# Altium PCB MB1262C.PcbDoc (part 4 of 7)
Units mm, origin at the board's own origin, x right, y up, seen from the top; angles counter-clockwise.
Board outline 208 x 250 mm, 6 copper layers (Top Layer, Layer 2, Layer 3, Layer 4, Layer 5, Bottom Layer), stack 1.596 mm thick; 483 components, 502 nets, 2134 pads, 1709 vias.
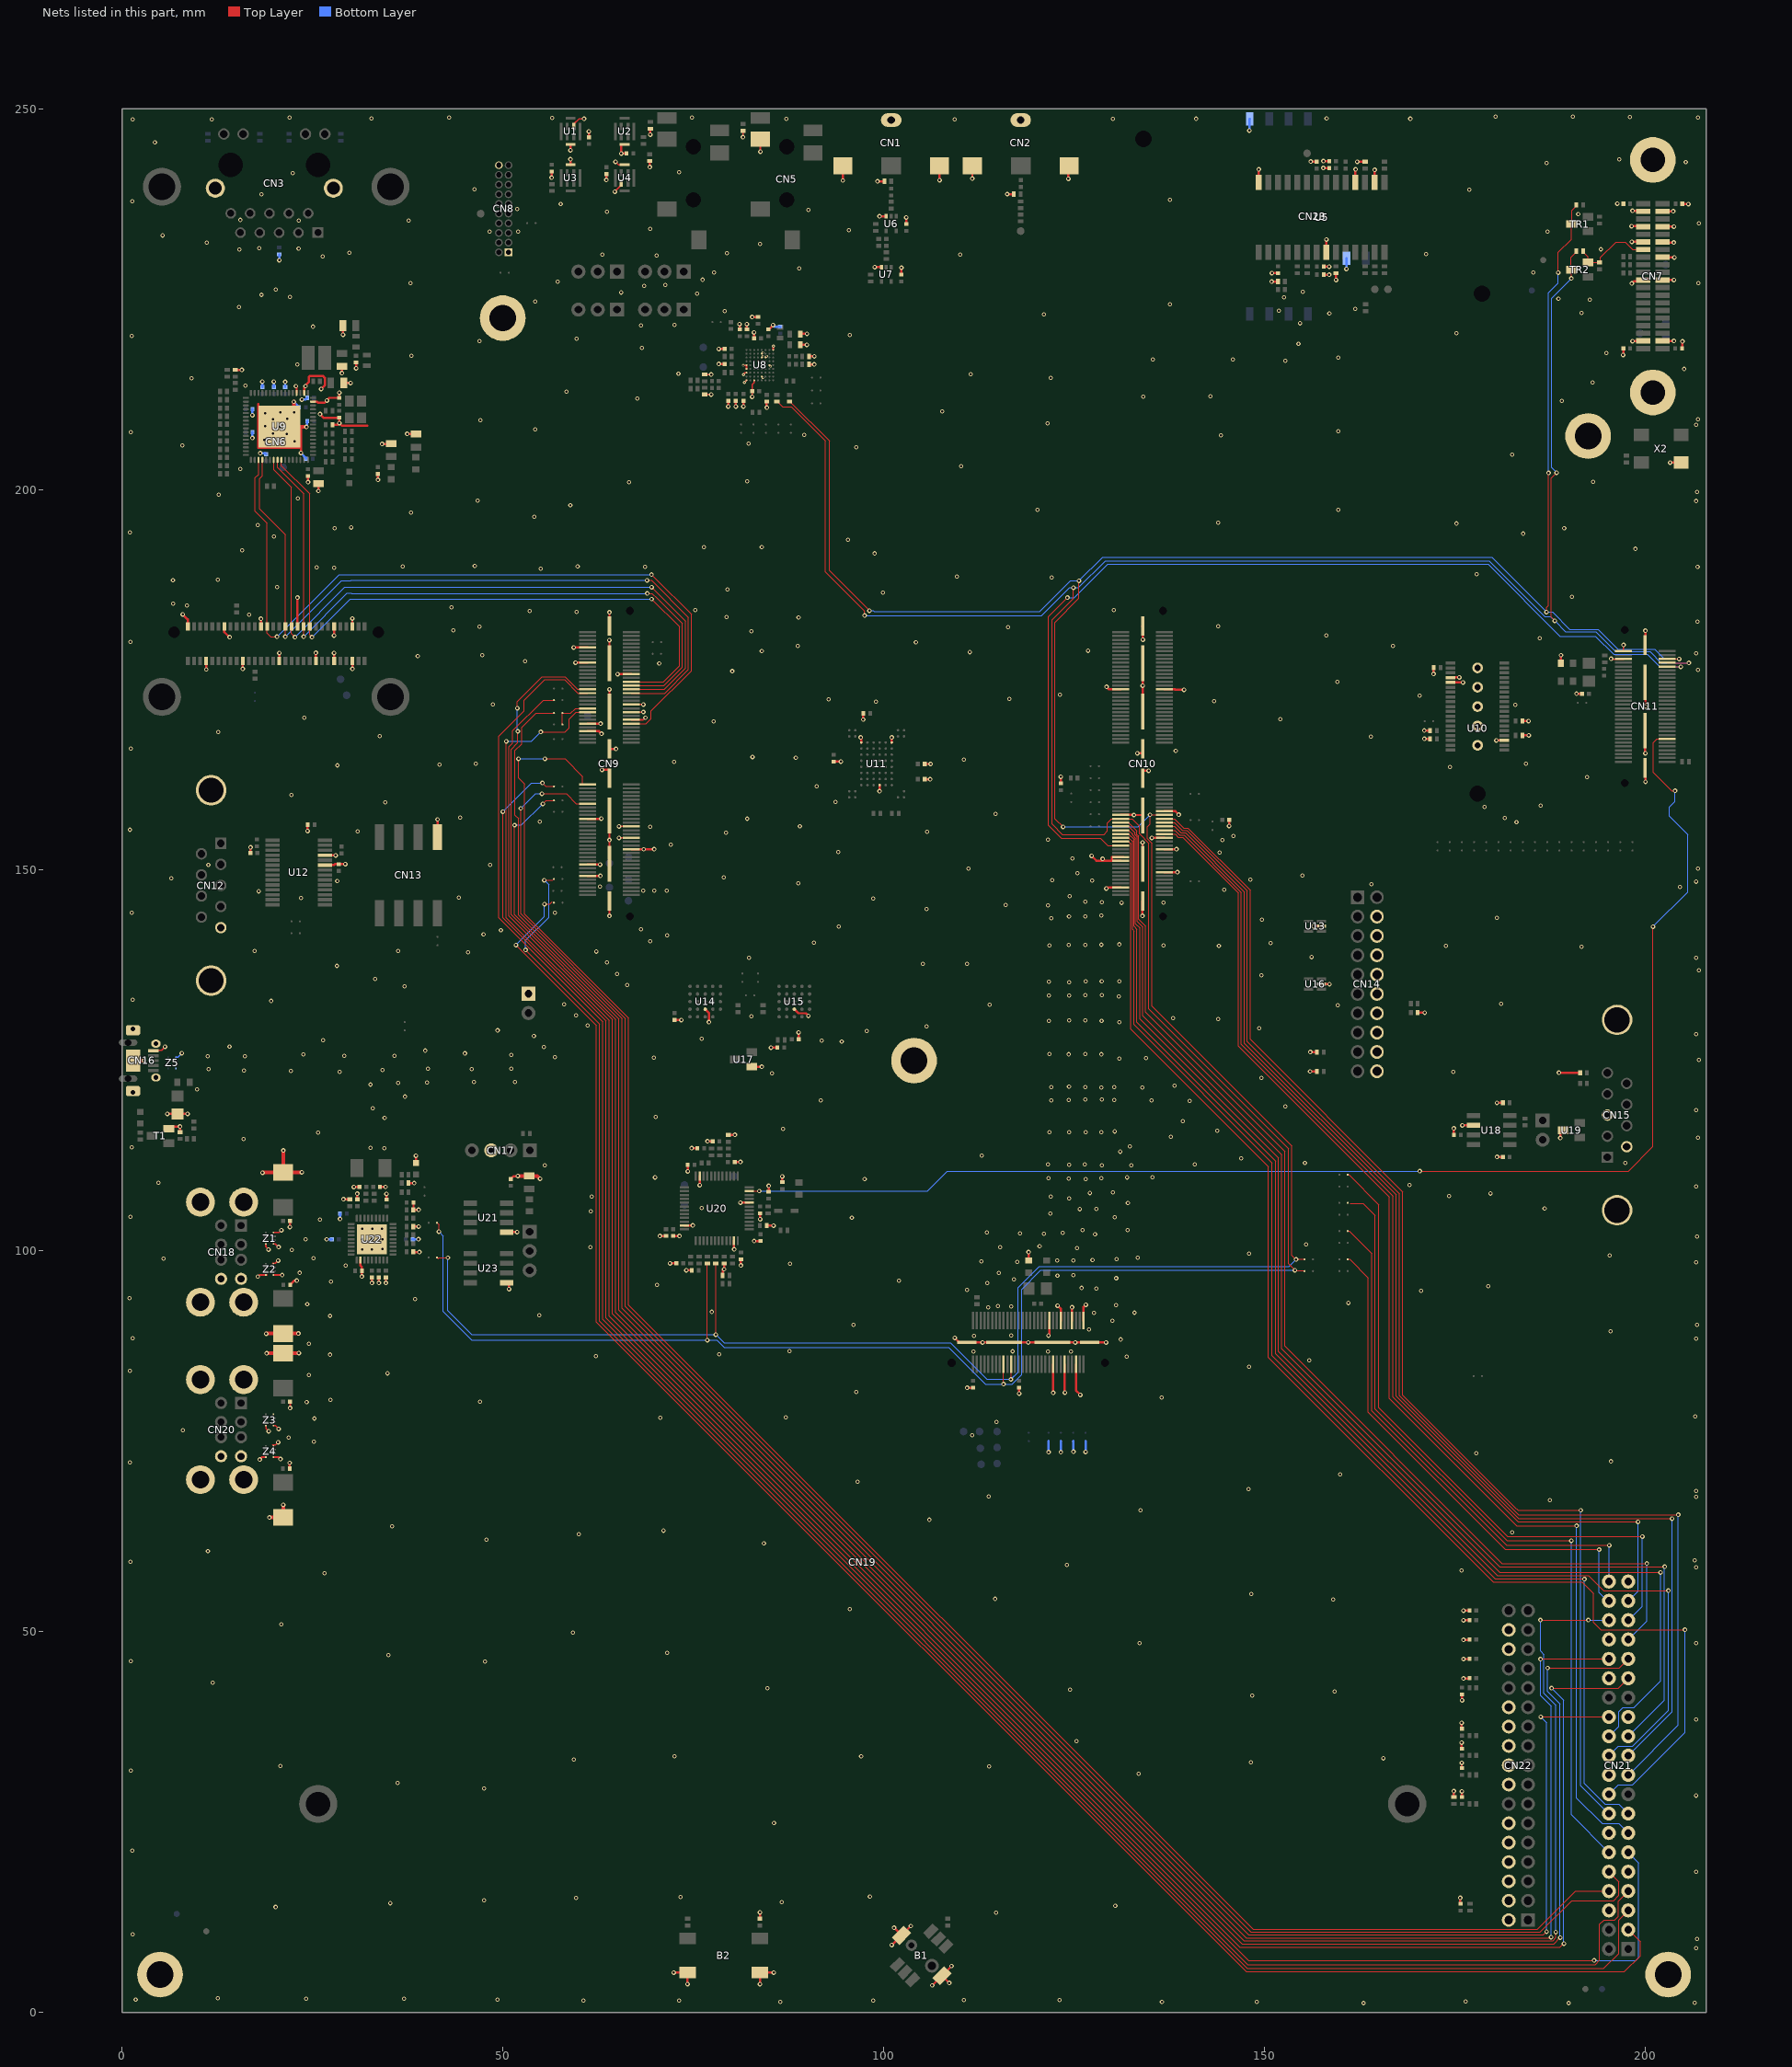
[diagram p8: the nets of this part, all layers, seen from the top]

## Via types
v1: diameter 0.6, hole 0.3, Top Layer to Bottom Layer, tented both sides, 979 vias
v2: diameter 0.55, hole 0.3, Top Layer to Bottom Layer, tented both sides, 687 vias
v3: diameter 0.3, hole 0.15, Top Layer to Bottom Layer, tented both sides, 31 vias
v4: diameter 0.4, hole 0.2, Top Layer to Bottom Layer, tented both sides, 12 vias

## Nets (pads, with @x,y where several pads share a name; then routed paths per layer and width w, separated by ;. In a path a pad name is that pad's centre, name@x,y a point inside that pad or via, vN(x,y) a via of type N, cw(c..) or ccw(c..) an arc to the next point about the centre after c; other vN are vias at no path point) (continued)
ETH_TX_EN: CN6.28 CN9.50 U9.35 | length 104
  Top Layer w0.13: U9.35@17.925,203.875 17.925,201.966 17.494,201.535 17.494,197.121 19.05,195.565 CN6.28@19.05,182.116 ; CN6.28@19.077,182.143 CN6.28@19.05,182.116 ; v1(20.353,180.655) 19.508,180.655 19.05,181.112 CN6.28@19.05,182 ; CN9.50@66.87,169.25 66.885,169.235 68.792,169.235 69.477,169.92 69.477,170.9 74.78,176.203 74.78,183.596 69.911,188.465 69.55,188.825 v1(69.528,188.822) ; CN6.28@19.05,182 19.094,182.044 CN6.28@19.05,182.087 ; CN6.28@19.05,182 CN6.28@19.05,182.087 ; CN6.28@19.05,182.087 19.036,182.102 CN6.28@19.05,182.116 ; CN6.28@19.05,182.087 CN6.28@19.05,182.116
  Bottom Layer w0.13: v1(20.353,180.655) 28.518,188.82 29.106,188.82 ; 29.106,188.818 68.75,188.818 68.755,188.822 v1(69.528,188.822)
ETH_TXD0: CN6.34 CN9.34 U9.36 | length 98.4
  Top Layer w0.13: U9.36@18.425,203.875 18.425,201.766 18.063,201.405 18.063,197.412 21.45,194.026 CN6.34@21.45,182 21.45,180.67 v1(21.442,180.662) ; CN9.34@66.87,173.25 71.262,173.25 74.381,176.369 74.381,182.265 74.383,182.267 74.383,183.205 69.513,188.075 v1(68.95,188.075)
  Bottom Layer w0.13: v1(21.442,180.662) 28.825,188.046 30.044,188.046 ; 30.044,188.048 68.923,188.048 v1(68.95,188.075)
ETH_TXD1: CN6.36 CN9.32 U9.39 | length 94.7
  Top Layer w0.13: U9.39@19.925,203.875 19.925,202.593 21.642,200.875 22.25,200.268 CN6.36@22.25,182 22.25,181.068 v1(22.701,180.617) ; CN9.32@66.87,173.75 71.207,173.75 73.97,176.512 73.97,182.73 v1(69.55,187.15)
  Bottom Layer w0.13: v1(22.701,180.617) 29.226,187.141 30.022,187.141 ; 30.022,187.15 v1(69.55,187.15)
ETH_TXD2: CN6.40 CN9.30 U9.40 | length 91.8
  Top Layer w0.13: U9.40@20.425,203.875 20.425,202.863 23.85,199.438 CN6.40@23.85,182 v1(23.85,180.656) ; CN6.40@23.8,182.05 CN6.40@23.825,182.075 ; CN9.30@66.87,174.25 71.156,174.25 73.58,176.674 73.58,182.37 70.233,185.717 69.6,186.35 v1(68.975,186.35)
  Bottom Layer w0.13: v1(23.85,180.656) 29.552,186.357 30.154,186.357 ; 30.154,186.35 v1(68.975,186.35)
ETH_TXD3: CN6.42 CN9.28 U9.41 | length 89.1
  Top Layer w0.13: U9.41@20.925,203.875 20.925,203.138 24.65,199.413 CN6.42@24.65,182 24.65,180.891 v1(24.934,180.607) ; CN9.28@66.87,174.75 71.093,174.75 73.19,176.847 73.19,181.96 v1(69.55,185.6)
  Bottom Layer w0.13: v1(24.934,180.607) 24.961,180.607 29.946,185.593 30.588,185.593 ; 30.588,185.6 v1(69.55,185.6)
EXP_GPIO2: CN21.3 SB55.1 | length 239.2
  Top Layer w0.1: v1(51.728,140.183) 51.728,140.175 62.306,129.597 62.306,90.645 147.588,5.363 197.246,5.363 199.351,7.468 199.351,9.304 CN21.3@197.77,10.885 ; v1@55.515,145.566 56.192,145.566 56.479,145.852
  Bottom Layer w0.1: v1(51.728,140.183) 55.459,143.914 v1(55.459,145.553)
EXP_GPIO3: CN21.5 SB52.1 | length 240.7
  Top Layer w0.1: v1(52.999,139.54) 62.728,129.812 62.728,90.809 147.715,5.822 194.558,5.822 196.511,7.776 196.511,12.166 CN21.5@197.77,13.425 ; v1(55.437,148.693) 56.568,148.693 SB52.1@56.717,148.842
  Bottom Layer w0.1: v1(52.999,139.54) 52.999,140.79 56.045,143.836 56.045,148.085 v1(55.437,148.693)
EXP_GPIO4: CN9.33 CN21.7 | length 276.2
  Top Layer w0.1: CN9.33@61.13,173.25 59.879,173.25 58.108,175.021 55.537,175.021 52.813,172.297 52.813,170.922 49.472,167.581 49.472,143.737 63.128,130.081 63.128,91 147.808,6.32 193.426,6.32 193.989,6.883 193.989,11.594 194.577,12.183 195.978,12.183 196.456,12.661 196.456,14.651 CN21.7@197.77,15.965
EXP_GPIO5: CN9.43 CN21.29 | length 298.7
  Top Layer w0.1: v1(50.459,166.936) 50.459,143.773 63.96,130.272 63.96,91.448 146.792,8.617 188.801,8.617 189.285,9.1 v1(189.334,9.05) ; v1(54.99,168.154) 58.154,168.154 58.704,168.704 58.704,169.848 59.606,170.75 CN9.43@61.13,170.75 ; v1(187.703,42.603) 196.468,42.603 CN21.29@197.77,43.905
  Bottom Layer w0.1: v1(50.459,166.936) 53.773,166.936 v1(54.99,168.154) ; v1(187.703,42.603) 189.284,41.022 189.284,9.144 189.334,9.094 v1(189.334,9.05)
EXP_GPIO6: CN21.31 SB15.1 | length 295.7
  Top Layer w0.1: SB15.1@56.717,172.338 55.315,172.338 51.3,168.323 51.3,166.706 50.78,166.185 50.78,144.007 64.387,130.4 64.387,91.734 147.085,9.036 188.004,9.036 188.826,9.858 v1(188.834,9.85) ; v1(187.198,45.249) 196.574,45.249 CN21.31@197.77,46.445
  Bottom Layer w0.1: v1(187.198,45.249) 187.198,42.156 188.794,40.56 188.794,9.891 v1(188.834,9.85)
EXP_GPIO7: CN21.26 SB17.1 | length 280.6
  Top Layer w0.1: SB17.1@56.717,170.634 54.355,170.634 52.467,168.746 52.467,166.586 51.618,165.737 51.618,157.215 52.067,156.765 52.067,144.117 65.654,130.53 65.654,92.449 147.901,10.201 186.618,10.201 v1(187.049,10.633) ; v1(186.269,38.825) CN21.26@195.23,38.825
  Bottom Layer w0.1: v1(186.269,38.825) 187.041,38.053 187.041,10.641 v1(187.049,10.633)
EXP_GPIO8: CN10.85 CN21.24 | length 165
  Top Layer w0.1: CN10.85@131.13,155.25 132.168,155.25 132.674,154.744 132.674,154.615 133.075,154.214 133.075,142.976 133.643,142.408 133.643,130.471 151.863,112.251 151.863,86.826 180.881,57.808 v1@202.025,57.808
  Bottom Layer w0.1: CN21.24@195.23,36.285 196.516,37.571 196.516,39.515 197.065,40.063 198.5,40.063 202.024,43.587 v1@202.024,57.799
  other v1: 202.025,57.8
EXP_GPIO9: CN10.84 CN21.21 | length 164.9
  Top Layer w0.1: CN10.84@136.87,155.75 138.173,155.75 139.023,154.9 139.637,154.9 147.38,147.157 147.38,127.282 167.299,107.363 167.299,80.935 183.348,64.886 v1@203.514,64.886
  Bottom Layer w0.1: CN21.21@197.77,33.745 203.511,39.486 203.511,64.864 v1(203.514,64.864)
EXP_GPIO10: CN10.82 CN21.19 | length 169.1
  Top Layer w0.1: CN10.82@136.87,156.25 138.168,156.25 139.219,155.199 139.826,155.199 147.719,147.305 147.719,127.523 167.733,107.509 167.733,80.992 182.977,65.748 ; 182.978,65.75 183.346,65.382 v1@204.325,65.382
  Bottom Layer w0.1: CN21.19@197.77,31.205 204.325,37.76 v1(204.325,65.375)
EXP_GPIO11: CN10.83 CN21.23 | length 164.4
  Top Layer w0.1: CN10.83@131.13,155.75 132.164,155.75 132.986,154.928 132.986,154.668 133.275,154.379 133.275,143.288 134.034,142.53 134.034,130.871 152.241,112.663 152.241,87.179 180.896,58.525 v1@202.56,58.525
  Bottom Layer w0.1: CN21.23@197.77,36.285 202.522,41.037 202.522,58.522 202.553,58.553 v1(202.56,58.553)
EXP_GPIO12: CN21.32 SB27.1 | length 278.5
  Top Layer w0.1: v1(51.542,155.918) 51.542,144.164 65.235,130.471 65.235,92.207 147.625,9.817 v1@187.634,9.817 ; v1(55.266,158.721) 55.708,159.163 SB27.1@56.717,159.163 ; v1@186.249,46.445 CN21.32@195.23,46.445 ; v1(186.25,46.425) v1@186.25,46.444 ; v1(187.634,9.9) v1@187.639,9.895
  Bottom Layer w0.1: v1(51.542,155.918) 52.463,155.918 v1(55.266,158.721) ; v1(186.25,46.425) 186.25,41.653 187.639,40.263 187.639,9.906 v1(187.634,9.9)
EXP_GPIO13: CN10.81 CN21.33 | length 148.7
  Top Layer w0.1: CN10.81@131.165,156.285 CN10.81@131.13,156.25 132.165,156.25 133.269,155.146 133.269,154.708 133.475,154.502 133.475,143.575 134.4,142.65 134.4,131.343 152.681,113.062 152.681,87.526 181.22,58.987 v1(200.216,58.987)
  Bottom Layer w0.1: CN21.33@197.798,48.977 200.216,51.396 v1(200.216,58.987)
EXP_GPIO14: CN9.61 CN21.8 | length 253.5
  Top Layer w0.1: v1(52.068,164.622) 52.068,162.091 52.829,161.329 52.829,144.256 66.516,130.569 66.516,92.912 148.502,10.926 185.825,10.926 190.864,15.965 CN21.8@195.23,15.965 ; v1(55.535,164.616) 58.181,164.616 60.487,162.311 60.487,161.25 CN9.61@61.13,161.25
  Bottom Layer w0.1: v1(52.068,164.622) 52.074,164.616 v1(55.535,164.616)
EXP_GPIO15: CN9.71 CN21.10 | length 251.4
  Top Layer w0.1: v1(52.346,158.121) 52.346,144.292 66.088,130.549 66.088,92.704 148.222,10.571 186.208,10.571 190.354,14.716 195.853,14.716 196.55,15.413 196.55,17.185 CN21.10@195.23,18.505 ; v1(55.132,160.051) 58.346,160.051 59.647,158.75 CN9.71@61.13,158.75
  Bottom Layer w0.1: v1(52.346,158.121) 52.353,158.121 54.283,160.051 v1(55.132,160.051)
EXP_GPIO16: CN9.31 CN21.36 | length 306.9
  Top Layer w0.1: v1(51.92,171.278) 51.92,172.154 55.178,175.412 58.17,175.412 59.832,173.75 CN9.31@61.13,173.75 ; v1(51.97,168.237) 51.97,166.741 51.092,165.862 51.092,144.155 64.819,130.428 64.819,91.946 147.334,9.431 187.888,9.431 188.287,9.83 188.287,10.481 188.259,10.509 v1(188.259,10.576) ; v1(186.236,51.547) 186.248,51.535 v1(192.533,51.535)
  Bottom Layer w0.1: v1(51.92,171.278) 51.92,168.288 v1(51.97,168.237) ; v1(186.236,51.547) 186.236,47.481 186.7,47.016 186.7,41.913 188.259,40.354 v1(188.259,10.576) ; v1(192.533,51.535) 192.523,51.525 CN21.36@195.23,51.525
EXP_GPIO17: CN21.11 SB23.1 | length 265.6
  Top Layer w0.1: v1(50.004,157.675) 50.004,143.767 63.549,130.222 63.549,91.204 147.907,6.847 v1(193.286,6.847) ; v1(55.205,161.446) 55.654,160.998 SB23.1@56.717,160.998
  Bottom Layer w0.1: v1(50.004,157.675) 53.776,161.446 v1(55.205,161.446) ; v1(193.286,6.847) 198.775,6.847 199.156,7.228 199.156,19.659 CN21.11@197.77,21.045
EXP_GPIO18: CN21.12 SB66.1 | length 105.3
  Top Layer w0.1: 161.267,106.262 162.962,106.262 164.545,104.679 164.545,79.258 181.837,61.966 v1@190.3,61.966
  Bottom Layer w0.1: v1(190.3,61.975) 190.291,61.966 190.291,25.984 CN21.12@195.23,21.045
EXP_GPIO19: CN21.35 SB63.1 | length 85.7
  Top Layer w0.1: SB63.1@161.015,110.023 161.091,110.023 165.031,106.084 165.031,79.404 181.928,62.506 199.615,62.506 v1(199.625,62.497)
  Bottom Layer w0.1: CN21.35@197.77,51.525 199.614,53.369 v1@199.614,62.497
EXP_GPIO20: CN21.38 SB73.1 | length 66.6
  Top Layer w0.1: SB73.1@160.937,98.915 161.173,98.915 163.604,96.484 163.604,78.807 181.595,60.816 193.953,60.816 v1(193.937,60.8)
  Bottom Layer w0.1: v1(193.937,60.8) 193.937,55.177 CN21.38@195.223,53.891
EXP_GPIO21: CN21.40 SB69.1 | length 68.2
  Top Layer w0.1: SB69.1@160.937,102.618 161.121,102.618 164.099,99.64 164.099,79.033 181.783,61.35 v1(195.275,61.35)
  Bottom Layer w0.1: CN21.40@195.223,56.647 195.275,56.698 v1(195.275,61.35)
EXP_GPIO22: CN10.89 CN21.15 | length 164.2
  Top Layer w0.1: CN10.89@131.13,154.25 132.172,154.25 132.675,153.746 132.675,142.215 132.873,142.017 132.873,129.713 151,111.586 151,86.241 180.268,56.973 v1@192.009,56.973
  Bottom Layer w0.1: v1(192.009,56.928) 192.016,56.934 192.003,56.922 192.003,30.092 194.735,27.36 196.535,27.36 CN21.15@197.77,26.125
EXP_GPIO23: CN10.80 CN21.16 | length 160.7
  Top Layer w0.1: CN10.80@136.87,156.75 138.187,156.75 139.42,155.518 139.967,155.518 148.14,147.345 148.14,127.785 168.167,107.758 168.167,81.087 182.84,66.413 ; 182.837,66.409 183.308,65.938 v1@191.544,65.938
  Bottom Layer w0.1: v1(191.544,65.964) 191.544,29.811 CN21.16@195.23,26.125
EXP_GPIO24: CN10.91 CN21.18 | length 175.2
  Top Layer w0.1: CN10.91@131.13,153.75 132.17,153.75 132.475,153.445 132.475,129.113 150.534,111.055 150.534,86.011 180.023,56.522 191.71,56.522 193.218,55.014 193.218,51.231 194.183,50.267 v1@205.473,50.267
  Bottom Layer w0.1: CN21.18@195.23,28.665 196.473,29.908 198.35,29.908 205.222,36.78 v1(205.222,50.281)
EXP_GPIO25: CN10.87 CN21.22 | length 167.7
  Top Layer w0.1: CN10.87@131.13,154.75 132.167,154.75 132.167,154.757 132.875,154.049 132.875,142.64 133.252,142.263 133.252,130.014 151.458,111.808 151.458,86.511 180.589,57.38 192.558,57.38 194.553,55.385 v1@203.025,55.385
  Bottom Layer w0.1: CN21.22@195.23,33.745 196.487,35.002 198.344,35.002 203.026,39.684 v1(203.025,55.4)
EXP_GPIO26: CN10.86 CN21.37 | length 137.9
  Top Layer w0.1: CN10.86@136.87,155.25 138.235,155.25 138.877,154.608 139.465,154.608 146.979,147.094 146.979,127.132 166.888,107.223 166.888,80.83 183.287,64.431 v1@199.05,64.431
  Bottom Layer w0.1: CN21.37@197.77,54.065 199.044,55.339 199.044,63.998 ; 199.039,63.998 199.039,64.42 v1(199.051,64.431)
EXP_GPIO27: CN10.88 CN21.13 | length 163.4
  Top Layer w0.1: CN10.88@136.87,154.75 138.288,154.75 138.701,154.337 139.285,154.337 146.61,147.012 146.61,126.899 166.409,107.1 166.409,80.662 183.148,63.923 v1@190.993,63.923
  Bottom Layer w0.1: v1(190.993,63.917) 190.993,28.179 194.349,24.823 196.532,24.823 CN21.13@197.77,23.585
GND: B1.7 B1.8 B2.3 B2.4 C1.1 C2.1 C3.1 C4.2 C6.1 C7.1 C8.1 C11.2 C12.1 C13.2 C15.2 C16.2 C17.1 C18.2 C19.2 C20.1 C23.1 C24.1 C25.1 C26.2 C27.1 C28.2 C29.2 C30.2 C31.1 C32.1 C33.1 C35.1 C37.1 C40.1 C41.1 C42.1 C43.1 C44.1 C45.1 C46.1 C47.1 C48.1 C49.1 C50.1 C51.1 C54.1 C55.1 C56.1 C57.1 C58.1 C59.1 C60.1 C61.1 C64.1 C65.2 C66.1 C67.1 C68.1 C69.2 C70.1 C71.1 C72.1 C73.1 C74.1 C75.1 C76.2 C77.1 C78.1 C79.1 C80.1 C81.1 C82.1 C83.1 C84.1 C85.1 C86.1 C87.1 C88.1 C89.1 C90.1 C91.1 C92.1 C93.1 C94.1 C95.1 C96.1 C97.1 C99.1 C100.2 C102.2 C103.1 C104.1 C105.1 C106.1 C107.2 C108.2 C109.1 C110.1 C111.1 C112.1 C113.1 C114.1 C115.1 C116.1 C117.1 C118.1 C119.1 C120.1 C121.1 C122.1 C123.1 C124.1 C125.1 C126.1 C127.1 C128.1 C129.1 C130.1 C131.1 C132.1 C133.1 C134.1 CN1.1 CN1.2 CN1.3 CN2.1 CN2.2 CN2.3 CN3.15 CN3.16 CN5.3 CN6.2 CN6.7 CN6.14 CN6.19 CN6.26 CN6.31 CN6.38 CN6.43 CN6.49 CN6.50 CN6.55 CN6.56 CN7.3 CN7.4 CN7.7 CN7.8 CN7.11 CN7.12 CN7.16 CN7.21 CN7.22 CN7.37 CN7.38 CN7.41 CN7.42 CN8.1 CN8.20 CN9.9 CN9.17 CN9.24 CN9.40 CN9.44 CN9.48 CN9.49 CN9.53 CN9.79 CN9.84 CN9.90 CN9.96 CN9.103 CN9.109 CN9.121 CN9.122 CN9.123 CN9.124 CN9.125 CN9.126 CN9.127 CN9.128 CN10.31 CN10.32 CN10.76 CN10.77 CN10.90 CN10.96 CN10.99 CN10.101 CN10.108 CN10.115 CN10.121 CN10.122 CN10.123 CN10.124 CN10.125 CN10.126 CN10.127 CN10.128 CN11.56 CN11.60 CN11.61 CN11.62 CN11.63 CN11.64 CN12.5 CN12.MT1 CN12.MT2 CN13.7 CN14.4 CN14.6 CN14.8 CN14.10 CN14.12 CN14.14 CN14.16 CN14.18 CN14.20 CN15.3 CN15.6 CN15.MT1 CN15.MT2 CN16.5 CN16.6 CN16.7 CN16.8 CN16.9 CN16.10 CN17.3 CN18.B4 CN18.CH1 CN18.CH2 CN18.CH3 CN18.CH4 CN18.T4 CN19.1 CN19.6 CN19.7 CN19.12 CN19.13 CN19.18 CN19.19 CN19.61 CN19.62 CN19.63 CN19.64 CN20.B4 CN20.CH1 CN20.CH2 CN20.CH3 CN20.CH4 CN20.T4 CN21.6 CN21.9 CN21.14 CN21.20 CN21.25 CN21.30 CN21.34 CN21.39 CN22.2 CN22.4 CN22.6 CN22.8 CN22.10 CN22.12 CN22.16 CN22.18 CN22.20 CN22.22 CN22.24 CN22.30 CN22.32 CN23.C5 CN23.S1 H1.1 H2.1 H3.1 H4.1 H5.1 JP5.1 L3.2 L8.1 LD3.2 R1.1 R2.2 R4.2 R5.1 R7.1 R9.2 R24.1 R30.2 R36.1 R37.1 R39.1 R41.1 R47.2 R57.1 R76.2 R78.1 R79.2 R80.1 R81.2 R89.2 R91.2 R92.2 R93.1 R95.1 R98.2 R101.2 R108.1 R112.2 R114.1 R116.1 R117.1 R121.1 R126.1 R128.2 R135.1 SB78.2 SB79.2 SB80.2 SB81.2 T1.2 U1.2 U1.5 U2.5 U3.5 U4.2 U4.5 U5.2 U5.4 U5.14 U5.22 U6.3 U7.3 U8.A1 U8.A3 U8.A4 U8.A5 U8.C1 U8.D6 U8.E2 U8.E7 U8.E8 U8.F7 U8.G5 U8.H9 U9.2 U9.4 U9.63 U9.65 U10.5 U10.30 U10.32 U10.MT1 U10.MT2 U10.MT3 U10.MT4 U10.MT5 U11.C5 U11.K3 U11.K8 U12.23 U12.25 U13.2 U14.B3 U15.B3 U16.2 U17.1 U18.2 U19.3 U20.8 U20.23 U20.35 U20.47 U21.1 U22.11 U22.37 U23.1 X2.2 Z1.4 Z1.5 Z1.8 Z2.4 Z2.5 Z2.8 Z3.4 Z3.5 Z3.8 Z4.4 Z4.5 Z4.8 Z5.5 Z5.8 | length 465.6
  Top Layer w0.2: CN16.5@4.125,126.3 4.125,126.363 5.202,126.363 5.65,126.811 v1(5.644,126.818) ; v1(17.83,96.642) 18.048,96.86 19.002,96.86 ; Z1.4@18.892,100.924 18.892,100.554 v1(19.249,100.198) ; Z3.4@18.902,77.062 18.902,76.692 v1(19.258,76.336) ; 19.743,98.382 20.133,98.382 20.494,98.742 v1(20.494,98.754) ; 19.752,74.52 20.143,74.52 20.503,74.88 v1(20.503,74.892) ; Z2.5@19.892,96.849 21.025,96.849 v1(21.032,96.842) ; Z1.5@19.892,100.924 20.142,100.924 v1(20.554,100.511) ; Z1.8@19.892,102.424 20.637,102.424 20.931,102.718 v1(20.934,102.718) ; Z3.5@19.902,77.062 20.151,77.062 v1(20.564,76.649) ; U1.2@59.338,247.675 59.338,247.973 60.025,248.66 60.672,248.66 v1(60.677,248.665) ; v1(64,143.996) CN9.128@64,145.937 ; CN9.127@64,150.825 v1(64,153.964) CN9.126@64,157.175 ; v1(64.708,239.09) 64.708,239.112 65.55,239.954 U4.2@65.55,240.229 ; v1(64.804,243.022) 64.814,243.022 65.207,242.629 U4.5@66,242.629 ; v1(65.255,155.75) CN9.84@66.87,155.75 ; v1(65.263,154.25) CN9.90@66.87,154.25 ; v1(65.552,244.109) v1@65.561,244.1 ; U2.5@65.552,245.242 65.585,245.275 U2.5@66,245.275 ; CN9.48@66.87,169.75 66.873,169.747 68.446,169.747 v1(68.718,170.019) ; CN9.44@66.87,170.75 66.878,170.758 v1@68.439,170.758 ; CN9.40@66.87,171.75 66.906,171.786 v1@68.416,171.786 ; R47.2@76.504,212.463 v1(77.37,212.463) ; R41.1@76.504,215.088 v1(77.349,215.088) ; v1(81.535,246.25) R2.2@81.535,247.073 ; v4(81.573,216.3) 81.975,216.3 U8.A5@82,216.325 U8.A4@82,215.825 ; v4(81.613,215.09) 81.613,215.145 81.793,215.325 U8.A3@82,215.325 ; v4(81.723,214.05) 81.723,214.048 U8.A1@82,214.325 ; C40.1@82.65,212.9 82.755,213.005 82.755,213.765 83,214.01 U8.C1@83,214.325 ; v1(82.75,212.158) C40.1@82.75,212.9 ; U8.D6@83.5,216.825 v3@83.625,216.7 ; v1(83.811,244.354) CN5.3@83.811,245.835 ; U8.E2@84,214.825 v3(84.16,214.665) ; U8.E7@84,217.325 v3(84.16,217.485) ; U8.E8@84,217.825 v3@84.125,217.95 ; U8.F7@84.5,217.325 v3@84.625,217.45 ; U8.G5@85,216.325 v3@85.125,216.2 ; U8.H9@85.5,218.325 v4@85.5,218.787 ; v4@85.537,218.738 v4(85.537,218.824) ; 88.807,131.218 89.786,131.218 ; v1(195.527,177.754) 195.573,177.708 197.172,177.708 CN11.56@197.13,177.75 ; CN11.60@197.13,178.75 CN11.60@197.153,178.773 ; CN11.60@197.152,178.774 v1(197.152,179.579)
  Top Layer w0.25: v1(18.08,72.624) 18.393,72.937 Z4.4@18.892,72.937 ; Z4.5@19.892,72.937 20.559,72.937 v1(20.803,72.693) ; v1@22.063,79.38 C105.1@22.063,80.219 ; U9.4@22.916,212.684 v1@22.916,213.473 ; R114.1@38.275,105.4 38.275,105.405 C85.1@38.275,106.35
  Top Layer w0.3: v1(5.942,118.005) C69.2@7.279,118.005 7.281,118.003 v1(8.602,118.003) ; T1.2@6.145,116.061 6.145,116.287 6.192,116.334 v1(7.621,116.334) R98.2@7.621,115.614 ; v1(7.969,183.595) 8.645,182.919 CN6.2@8.645,181.995 ; CN6.7@11.05,177.5 11.05,176.376 v1(11.067,176.359) ; CN6.14@13.463,182.013 13.437,181.987 13.437,181.253 14.086,180.604 v1(14.136,180.604) ; R39.1@14.875,215.7 v1(15.735,215.7) ; CN6.19@15.85,177.5 15.865,177.485 v1(15.865,176.426) ; C64.1@16.875,152.275 v1(16.875,153.018) ; 17.87,211.237 17.87,205.472 23.48,205.472 ; v1(18.235,183.023) 18.235,182.078 18.302,182.011 18.27,181.98 CN6.26@18.25,182 ; CN6.31@20.65,177.5 20.65,178.509 v1(20.651,178.511) ; U9.65@20.675,208.275 U9.65@20.739,208.211 ; C106.1@22.019,71.435 v1(22.019,72.184) ; v1(22.042,103.14) 22.045,103.142 C87.1@22.045,103.931 ; C99.1@22.075,95.571 22.625,96.122 v1(22.959,96.122) ; U9.65@22.55,208.237 U9.65@22.576,208.211 ; v1(22.827,213.561) v1@22.916,213.473 ; CN6.38@23.05,182 23.045,182.005 23.053,182.014 v1(23.053,185.799) ; 23.465,208.211 23.48,208.196 23.48,205.472 ; v1(23.48,204.8) 23.48,205.472 ; U9.2@23.925,212.675 23.925,213.405 v1(24.083,213.564) 24.083,213.649 24.517,214.083 24.517,214.731 24.696,214.91 26.363,214.91 26.63,214.643 26.63,213.669 v1(26.145,213.184) ; v1(24.382,155.14) C61.1@24.382,155.973 ; v1(24.421,200.969) C50.1@24.421,201.745 ; U9.63@25.075,211.525 25.603,211.525 25.754,211.373 26.592,211.373 v1(26.907,211.688) 27.242,212.023 C45.1@28.533,212.023 28.538,212.028 v1(28.538,212.704) ; v1(25.442,178.556) 25.45,178.548 CN6.43@25.45,177.5 ; v1(25.791,199.795) C51.1@25.791,200.739 ; v1(25.996,209.881) 26.454,209.423 C46.1@28.533,209.423 v1(28.533,208.702) ; U12.23@26.65,150.675 27.853,150.675 27.976,150.798 v1(29.324,150.798) ; U12.25@26.65,151.975 28.043,151.975 v1(28.057,151.96) ; R57.1@27.637,208.497 28.328,208.497 v1(28.533,208.702) ; v1(27.849,178.514) 27.849,177.501 CN6.49@27.85,177.5 ; v1(27.848,180.818) 27.848,181.998 CN6.50@27.85,182 ; v1(28.859,215.256) C32.1@28.859,216.147 C32.1@28.881,216.125 ; v1(29.007,220.321) C20.1@29.007,221.505 ; v1(29.091,106.796) R112.2@29.913,106.796 ; C37.1@29.102,213.971 v1(30.027,213.971) ; v1(30.241,183.047) 30.241,182.009 CN6.56@30.25,182 ; v1(30.25,176.438) CN6.55@30.25,177.5 ; v1(30.435,108.414) C80.1@31.184,108.414 ; v1(30.73,215.905) C33.1@30.73,216.661 ; C83.1@30.904,106.796 v1(30.904,107.531) ; U22.11@31.325,98.8 31.325,98.062 31.508,97.88 v1(31.508,96.647) ; 32.231,208.35 28.886,208.35 v1(28.533,208.702) ; v1(32.825,95.808) C95.1@32.825,96.535 ; v1(33.598,201.256) C49.1@33.598,202.023 ; v1(33.725,95.805) C96.1@33.725,96.535 ; C81.1@33.879,108.414 34.604,108.414 v1(34.612,108.421) ; v1(34.163,205.982) 35.328,205.982 C48.1@35.342,205.995 ; v1(34.65,95.811) C97.1@34.65,96.535 ; C84.1@34.735,106.762 v1(34.735,107.507) ; v1(37.442,207.285) 38.56,207.285 C47.1@38.588,207.257 ; R108.1@37.625,108.93 v1(38.366,108.93) ; R121.1@38.256,99.905 38.311,99.85 v1(39.05,99.85) ; R117.1@38.256,103.205 v1(38.946,103.205) ; R114.1@38.256,105.405 38.275,105.405 v1(38.944,105.405) ; LD3.2@38.59,111.542 v1(38.59,112.515) ; CN13.7@41.435,154.35 v1(41.435,156.672) ; U23.1@50.49,95.844 50.808,95.527 v1(50.808,94.997) ; U21.1@50.49,102.482 v1(51.885,102.482) ; C78.1@51.041,109.457 51.406,109.822 v1@51.96,109.822 ; v1(56.419,240.941) C6.1@56.419,241.742 ; U3.5@58.888,242.629 v1(58.888,243.353) ; v1(58.888,244.519) U1.5@58.888,245.275 ; v1(59.305,179.25) CN9.9@61.13,179.25 ; v1(59.558,177.25) CN9.17@61.13,177.25 ; CN9.109@61.13,149.25 v1(62.802,149.25) ; CN9.103@61.13,150.75 v1(62.77,150.75) ; CN9.79@61.13,156.75 62.903,156.75 v1(62.918,156.766) ; CN9.53@61.13,168.25 62.617,168.25 v1(62.955,167.912) ; CN9.49@61.13,169.25 v1(62.839,169.25) ; C1.1@61.3,246.246 v1(61.3,247.009) ; v1(63.031,163.17) 63.886,163.17 64,163.056 CN9.125@64,162.062 ; v1(63.6,240.637) C7.1@63.6,241.4 ; v1(63.984,180.223) 64,180.206 CN9.122@64,177.175 ; CN9.124@64,165.937 v1(64.87,165.937) ; CN9.123@64,170.825 v1(64,173.748) ; CN9.121@64,182.062 v1(64,183.874) ; v1(65.085,175.73) 65.105,175.75 CN9.24@66.87,175.75 ; v1(65.552,244.109) U2.5@65.552,245.242 ; v1@65.561,244.1 C2.1@66.25,244.1 ; CN9.96@66.92,152.764 v1(69.862,152.764) ; v1@68.416,171.786 v1(68.444,171.758) ; v1@68.439,170.758 v1(68.455,170.775) ; v1(69.291,242.313) R4.2@69.291,243.11 ; v1(69.359,246.591) R1.1@69.359,247.354 ; v1(70.626,101.975) C88.1@71.425,101.975 ; v1(71.956,98.378) C92.1@72.8,98.378 ; C89.1@72.375,101.975 v1(73.207,101.975) ; v1(72.442,5.25) B2.3@74.25,5.25 v1(74.25,3.754) ; C66.1@72.538,130.337 v1(73.424,130.337) ; U20.35@73.85,103.35 v1(74.954,103.35) ; v1(74.098,97.479) 74.806,97.479 C93.1@74.822,97.464 ; v1(74.275,110.451) C75.1@74.275,111.3 ; v1(74.797,113.5) C72.1@75.55,113.5 ; v1(75.85,108.649) U20.23@75.85,109.85 ; U14.B3@76.575,131.75 77.054,131.271 v1(77.054,130.068) ; v1(76.867,114.409) C71.1@77.549,114.409 ; v1(78.364,218.45) C31.1@79.125,218.45 ; v1(78.365,216.475) C35.1@79.125,216.475 ; R128.2@78.86,96.798 78.86,97.41 v1(79.06,97.61) R126.1@79.06,98.373 ; v1(79.595,210.877) C41.1@79.595,211.643 ; R101.2@79.6,115.25 v1(80.473,115.25) ; U20.47@80.35,101.35 80.35,100.247 v1(80.384,100.213) ; C74.1@80.45,111.7 v1(81.208,111.7) ; v1(80.595,210.882) C42.1@80.595,211.643 ; v1(81.071,221.699) 81.125,221.645 C23.1@81.125,221.025 ; v1(81.207,106.35) U20.8@82.35,106.35 ; v1(81.27,98.105) C91.1@81.27,98.924 ; v1(81.595,210.891) C43.1@81.595,211.643 ; C24.1@82.05,221.025 v1(82.05,221.704) ; U17.1@82.7,124.2 v1(84,124.2) ; v1(82.75,222.643) C19.2@83.514,222.643 ; v1(82.989,220.617) 82.989,220.031 82.904,219.946 C27.1@83,219.85 ; v1(82.994,101.31) C90.1@83.837,101.31 ; v1(83.75,3.742) B2.4@83.75,5.25 v1(85.587,5.25) ; C119.1@83.75,12.325 v1(83.75,13.164) ; v1(83.8,104.171) C86.1@83.8,104.95 ; C44.1@84.65,211.525 84.65,210.757 v1(84.66,210.747) ; R116.1@84.66,103.34 v1(85.555,103.34) ; C25.1@84.85,221.025 84.945,221.025 v1(85.497,221.577) ; C82.1@84.9,107.775 v1(84.9,108.542) ; v1(85.2,126.7) C68.1@86.05,126.7 ; v4@85.5,218.787 v4(85.537,218.824) ; C79.1@86.7,109.05 v1(86.7,109.8) ; U15.B3@88.275,131.75 88.807,131.218 ; v1@88.789,128.747 v1(88.85,128.686) C67.1@88.85,127.825 ; C28.2@89.073,218.996 89.863,218.996 v1(89.937,218.987) ; C26.2@89.075,220.375 89.144,220.444 v1(89.937,220.444) ; 89.786,131.218 v1(90.122,130.881) ; R37.1@90.2,216.425 v1(90.902,216.425) ; R36.1@90.2,217.475 v1(90.904,217.475) ; C56.1@93.456,164.267 v1(94.38,164.267) ; v1(94.65,240.557) CN1.2@94.65,242.5 ; v1@96.879,167.433 v1(96.979,167.433) 97.075,167.337 U11.K8@97.075,166.775 ; v1(97.328,169.779) C55.1@97.327,170.589 ; v1(98.833,229.197) 98.836,229.2 U7.3@99.7,229.2 ; v1(99.187,240.441) 99.196,240.45 R7.1@100.1,240.45 ; v1@99.475,160.383 U11.C5@99.475,161.175 ; v1(99.478,235.851) v1(99.478,235.851) U6.3@100.35,235.85 ; v1(101.063,167.443) 101.08,167.427 101.08,166.78 U11.K3@101.075,166.775 ; v1(101.08,8.883) B1.7@102.348,10.152 ; v1(101.364,11.136) B1.7@102.348,10.152 ; C18.2@102.325,228.2 v1(102.326,229.113) ; v1(102.962,235.72) 102.975,235.707 C13.2@102.975,234.85 ; v1(103.567,11.37) B1.7@102.348,10.152 ; C57.1@105.4,163.95 v1(106.16,163.95) ; C58.1@105.402,161.95 v1(106.101,161.95) v1@106.12,161.931 ; v1(106.382,3.578) B1.8@107.652,4.848 ; v1(107.35,240.595) CN1.3@107.35,242.5 ; v1(108.603,3.893) 108.603,3.897 B1.8@107.652,4.848 ; v1(108.918,6.114) B1.8@107.652,4.848 ; v1@109.327,88.613 109.94,88 CN19.64@110.937,88 CN19.63@115.825,88 118.98,88 v2@118.99,87.99 ; v1@110.956,81.965 110.965,81.965 111.05,82.05 C103.1@111.75,82.05 ; v1(111.634,240.803) 111.65,240.819 CN2.2@111.65,242.5 ; v1(116.213,238.776) 116.215,238.775 R9.2@117.1,238.775 ; C104.1@117.8,82.05 117.8,81.314 v1@117.802,81.312 ; v2@118.97,87.969 v2@118.99,87.99 ; L8.1@119.05,98.75 v1@119.05,99.845 ; v1@121.644,88.895 121.75,89.001 CN19.19@121.75,90.87 ; CN19.62@122.071,87.944 CN19.62@122.127,88 ; CN19.18@122.236,85.12 122.25,85.106 122.25,81.386 v1(122.262,81.374) ; v1@122.83,92.844 123.25,92.423 CN19.13@123.25,90.87 ; C59.1@123.262,161.408 v1(123.262,162.263) ; CN19.12@123.75,85.137 123.75,81.371 123.779,81.4 v1(123.8,81.4) ; v1(124.271,240.78) 124.271,242.421 CN2.3@124.35,242.5 ; v1@124.734,92.601 124.75,92.585 CN19.7@124.75,90.87 ; v1@125.142,88 CN19.62@122.175,88 CN19.62@122.127,88 ; v1(125.159,87.983) 126.979,87.983 CN19.61@126.981,87.981 ; 125.249,82.724 125.25,82.726 CN19.6@125.25,85.13 ; 125.25,83.13 125.25,81.69 v1(125.822,81.118) ; CN19.1@126.25,90.87 126.25,92.643 v1@126.538,92.932 ; CN19.61@127.063,88 129.193,88 v1@129.209,87.984 ; v1(127.301,151.896) 127.301,151.867 127.922,151.245 128.524,151.245 ; v1@128.762,151.483 128.524,151.245 ; v1(128.762,151.49) 129.005,151.247 129.035,151.247 ; v1@128.784,151.498 129.035,151.247 ; v1@129.222,147.585 v1@129.387,147.75 ; v1(129.23,147.593) v1@129.386,147.75 ; v1(129.282,174.075) 129.282,174.036 129.568,173.75 CN10.31@131.13,173.75 ; 129.709,147.75 v1@129.387,147.75 ; CN10.115@131.13,147.75 v1@129.387,147.75 ; CN10.101@131.13,151.25 CN10.101@129.995,151.25 ; CN10.77@131.13,157.25 132.854,157.25 v1(132.857,157.247) 133.928,157.247 CN10.126@134.008,157.167 ; CN10.99@131.474,151.75 CN10.99@131.13,151.75 CN10.99@131.13,151.75 129.995,151.751 CN10.101@129.995,151.25 ; v1(133.313,165.345) 134.025,165.345 134.025,165.937 CN10.124@134,165.937 ; v1(133.985,144.011) 133.985,145.922 CN10.128@134,145.937 ; v1(133.996,153.625) 133.996,150.855 134.013,150.838 CN10.127@134,150.825 ; CN10.125@134,162.062 134,162.995 134.066,163.062 v1(134.789,163.062) ; CN10.123@134,170.825 v1(134,174.236) CN10.122@134,177.284 ; CN10.122@134,177.175 CN10.122@134,177.284 ; CN10.121@134,182.062 133.974,182.037 134.031,181.979 v1(134.031,180.265) ; v1(135.205,154.241) 135.213,154.25 CN10.90@136.87,154.25 ; CN10.108@136.87,149.75 CN10.108@136.87,149.75 v1(138.578,149.749) ; CN10.96@136.87,152.75 136.89,152.77 136.91,152.75 v1(138.456,152.75) ; CN10.32@136.87,173.75 138.236,173.75 138.301,173.685 138.773,173.685 138.772,173.684 139.424,173.684 v1(139.433,173.693) ; CN10.76@136.872,157.752 CN10.76@136.87,157.75 138.309,157.75 v1(138.756,157.302) ; v1(145.372,155.817) 145.375,155.821 C60.1@145.375,156.62 ; U5.14@149.245,240.315 149.245,242.019 v1(149.253,242.028) ; v1(150.937,227.3) R30.2@151.775,227.3 ; v1(150.992,228.398) 150.994,228.4 C16.2@151.775,228.4 ; v1(155.998,123.577) 155.998,123.575 R92.2@156.875,123.575 ; v1(156.022,126.133) 156.03,126.125 R91.2@156.875,126.125 ; v1(156.072,243.04) 156.087,243.025 C4.2@156.875,243.025 ; v1(156.45,142.644) 157.494,142.644 U13.2@157.5,142.65 ; U16.2@157.5,135.05 v1(158.547,135.05) ; v1(157.73,242.209) 157.764,242.175 C8.1@158.5,242.175 ; v1(157.754,243.113) 157.767,243.1 C3.1@158.5,243.1 ; C17.1@157.775,228.2 158.503,228.2 v1(158.51,228.193) ; C15.2@157.775,229.25 158.486,229.25 v1(158.495,229.241) ; U5.22@158.135,231.135 158.135,232.808 v1(158.139,232.812) ; R24.1@159.4,228.4 159.4,227.521 v1(159.412,227.509) ; U5.4@161.945,240.315 161.945,241.998 v1(161.961,242.014) ; v1(162.172,243.018) 162.179,243.025 R5.1@163.225,243.025 ; U5.2@164.485,240.315 v1(164.485,241.956) ; R89.2@170.125,131.3 171.042,131.3 v1(171.047,131.304) ; v1(170.984,168.345) 171.005,168.325 R79.2@171.75,168.325 ; v1(170.989,167.25) R81.2@171.75,167.25 ; v1(172.202,175.785) 172.202,176.578 R76.2@172.238,176.613 ; U10.30@174.47,174.675 174.473,174.678 174.483,174.667 v1(176.086,174.667) ; U10.32@174.47,175.31 174.486,175.326 v1(175.599,175.326) ; v1(174.854,116.094) 174.875,116.073 C70.1@174.875,115.25 ; R135.1@174.873,28.294 v1(174.873,29.072) ; v1(175.723,15.057) 175.723,14.309 C118.1@175.747,14.285 ; C114.1@175.89,37.28 C114.1@175.927,37.28 175.903,37.303 v1(175.903,38.052) ; v1(175.903,35.437) 175.903,34.688 C115.1@175.927,34.665 ; v1(175.907,32.8) 175.907,32.291 175.822,32.206 C116.1@175.927,32.101 ; C117.1@175.927,28.294 v1(175.927,29.049) ; C113.1@175.927,41.771 175.951,41.747 v1(175.951,40.999) ; v1(175.987,116.498) 175.998,116.51 U18.2@177.45,116.51 ; v1(176.146,43.876) 176.894,43.876 C112.1@176.918,43.9 ; v1(176.146,46.426) 176.894,46.426 C111.1@176.918,46.45 ; v1(176.146,48.951) 176.894,48.951 C110.1@176.918,48.975 ; v1(176.146,51.501) 176.894,51.501 C109.1@176.918,51.525 ; v1(176.146,52.776) 176.894,52.776 C108.2@176.918,52.8 ; v1(180.445,167.033) 180.467,167.055 U10.5@181.53,167.055 ; v1(180.527,119.454) 181.279,119.454 R95.1@181.3,119.475 ; v1(180.542,112.367) 180.559,112.35 C73.1@181.3,112.35 ; R80.1@183.875,167.7 184.652,167.7 v1@184.69,167.737 ; R78.1@183.875,169.6 184.564,169.6 v1@184.7,169.464 ; v1(188.667,123.425) 188.667,123.389 188.678,123.4 R93.1@191.45,123.4 ; v1(188.833,114.841) 188.833,115.483 U19.3@189.2,115.85 ; L3.2@188.925,177.175 188.833,177.267 188.93,177.363 v1(188.93,178.233) ; v1(190.975,173.175) C54.1@191.7,173.175 ; v1(197.09,217.647) 197.125,217.682 C30.2@197.125,218.5 ; v1(198.207,234.57) 199.655,234.57 CN7.7@199.725,234.5 ; v1(198.228,227.048) 198.518,227.338 199.563,227.338 CN7.21@199.725,227.5 ; v1(198.248,232.501) 199.724,232.501 CN7.11@199.725,232.5 ; v1(198.327,236.587) 199.637,236.587 CN7.3@199.724,236.499 ; v1(198.34,219.473) 199.698,219.473 CN7.37@199.725,219.5 ; CN11.61@200,163.437 200.023,163.415 200.023,162.4 199.971,162.348 200.008,162.312 200.008,161.64 v1(200.033,161.614) ; CN11.62@200,168.325 200,165.383 v1(200.024,165.36) ; CN11.63@200,174.675 200.011,174.664 v1(200.011,171.519) ; CN11.64@200,179.562 200.031,179.593 200.019,179.605 v1(200.019,181.443) ; CN7.38@202.275,219.5 202.28,219.505 v1(203.754,219.505) ; CN7.22@202.275,227.5 202.282,227.493 v1(203.75,227.493) ; CN7.16@202.275,230.5 202.329,230.446 v1(203.814,230.446) ; CN7.12@202.275,232.5 202.357,232.418 v1(203.749,232.418) ; CN7.8@202.275,234.5 202.306,234.469 202.331,234.494 v1(203.776,234.494) ; CN7.4@202.275,236.5 202.322,236.547 202.444,236.424 202.556,236.536 v1(203.671,236.536) ; v1(203.265,203.527) 204.697,203.527 X2.2@204.72,203.55 ; C29.2@204.841,218.518 204.841,219.409 v1(204.869,219.437) ; C12.1@204.875,237.5 204.915,237.46 v1(205.656,237.46) ; v2@118.99,87.99 119,88 CN19.62@122.127,88 ; 128.524,151.245 129.036,151.245 ; 129.035,151.247 129.036,151.245 ; 129.035,151.247 129.568,151.247 129.569,151.245 ; 129.036,151.245 129.569,151.245 ; 129.569,151.245 129.574,151.25 CN10.101@129.995,151.25 ; 129.569,151.245 129.995,151.245 CN10.101@129.995,151.25
  Top Layer w0.5: CN16.10@1.45,125 v1(2.902,125) ; v1(18.461,110.29) 18.502,110.331 C76.2@21.17,110.331 ; v1(18.937,89.151) 18.952,89.166 C100.2@21.17,89.166 23.155,89.166 v1(23.158,89.163) ; v1(18.998,86.579) 19.014,86.595 23.216,86.595 v1(23.22,86.591) ; v1(19.366,65.012) C107.2@21.17,65.012 v1(21.17,66.67) ; U9.65@20.739,208.211 22.576,208.211 23.465,208.211 v1(24.216,208.211) ; v1(21.182,113.195) 21.17,113.183 C76.2@21.17,110.331 ; U9.65@22.55,208.237 v1(22.55,211.511) ; v1(23.601,110.328) 23.599,110.331 C76.2@21.17,110.331 ; v1(51.975,109.85) C77.1@53.458,109.85 54.531,109.85 v1(54.901,109.479)
  Bottom Layer w0.2: Z5.5@7.074,125.463 7.343,125.463 v1(7.847,125.967)
  Bottom Layer w0.3: v1(17.125,206.753) C129.1@17.125,207.525 ; v1(17.125,209.744) C127.1@17.125,210.525 ; v1(18.162,204.768) 18.798,204.768 C130.1@18.935,204.631 ; C124.1@18.425,213.432 v1(18.425,214.142) ; v1(19.917,214.156) 19.917,213.49 19.95,213.457 C123.1@19.925,213.432 ; v1(20.646,230.081) C120.1@20.646,230.866 ; C122.1@21.425,213.432 v1(21.425,214.118) ; v1(22.55,211.511) 23.251,210.81 C126.1@23.235,210.794 ; v1(23.48,204.8) 24.155,204.126 C131.1@24.155,204.023 ; v1(23.6,211.8) 24.078,211.8 C125.1@24.306,212.028 ; v1(24.216,208.211) 24.265,208.26 24.265,208.908 C128.1@24.335,208.978 ; v1(26.864,101.536) 27.536,101.536 C134.1@27.55,101.55 ; v1(28.617,104.208) C132.1@28.617,104.935 ; C133.1@38.15,101.55 v1(38.936,101.55) ; v1(85.497,221.577) 85.746,221.327 86.398,221.327 C121.1@86.45,221.275 ; v1(121.65,73.579) SB81.2@121.65,75.025 ; v1@123.275,73.585 SB80.2@123.275,75.025 ; SB79.2@124.9,75.025 124.9,73.667 v1(124.924,73.643) ; v1(126.523,73.609) 126.525,73.61 SB78.2@126.525,75.025 ; v1(148.012,247.126) 148.012,248.602 CN23.C5@148.08,248.67 ; v1(160.772,228.945) 160.78,228.953 CN23.S1@160.78,230.36
  other v1: 123.274,73.584 22.062,79.38 117.79,81.295 110.963,82.034 112.982,87.999 129.22,87.995 109.35,88.607 121.644,88.899 124.75,92.626 122.836,92.833 126.543,92.95 119.033,99.846 32.825,101.55 39.814,126.315 49.318,128.977 99.474,160.382 184.719,167.708 184.692,169.578 196.339,237.521
  other v2: 162.995,1.253 189.926,1.253 206.503,1.282 86.439,1.41 136.534,1.41 149.018,1.41 176.421,1.489 60.607,1.567 73.17,1.567 98.61,1.567 110.544,1.646 123.107,1.646 1.797,1.724 49.3,1.724 24.174,1.803 37.051,1.803 12.554,1.882 206.68,8.493 206.772,9.702 1.403,10.286 114.751,13.124 20.158,13.873 130.431,14.01 35.24,14.36 86.613,14.524 47.525,14.725 59.633,15.077 73.344,15.188 98.186,15.251 206.68,18.493 1.325,21.279 85.618,24.918 206.68,28.493 47.525,29.442 36.213,30.172 133.466,31.333 1.168,31.8 113.866,32.345 20.766,32.361 148.244,32.849 59.301,33.211 165.604,33.384 72.57,33.653 97.036,33.644 125.329,35.659 206.68,38.493 148.424,41.61 159.217,42.15 124.495,42.436 84.733,42.61 11.887,43.308 47.646,46.105 1.177,46.163 34.997,46.957 71.555,47.268 206.68,48.493 133.592,48.531 59.191,49.908 20.888,50.971 95.542,52.957 159.008,54.273 114.625,54.336 148.251,54.997 26.587,57.676 175.898,58.053 206.68,58.493 124.053,58.8 1.079,59.18 206.521,59.389 11.279,60.579 84.291,61.629 47.846,62.108 59.965,62.845 182.537,63.047 71.102,63.279 35.483,63.863 106.024,64.724 133.719,65.981 187.46,67.315 206.697,67.723 113.82,67.786 206.68,68.493 147.906,68.73 96.607,69.73 159.949,70.68 1.047,72.225 195.497,72.394 177.785,73.45 25.199,74.957 21.899,75.503 111.608,75.789 7.978,76.477 114.83,77.583 25.274,78.012 70.649,78.081 87.187,78.181 206.557,78.311 24.259,80.157 47.023,80.202 27.38,80.455 136.501,80.776 96.412,81.475 24.514,83.73 34.875,83.932 1.047,84.272 147.992,84.794 155.889,85.66 131.886,86.132 62.228,86.203 27.325,86.404 78.405,86.451 111.775,86.801 121.586,86.813 124.59,86.813 87.656,86.837 116.933,86.829 24.514,87.851 119.001,87.98 131.117,88.398 206.68,88.493 1.382,88.56 111.859,88.853 116.757,88.9 195.418,89.433 126.978,89.702 96.023,90.299 206.816,90.316 130.041,90.854 27.325,91.48 54.813,91.588 127.639,91.858 132.96,91.903 77.415,92.02 113.745,92.615 116.755,92.738 115.016,92.805 130.521,92.917 24.323,93.009 161.034,93.172 38.459,93.674 0.982,93.794 170.589,94.746 110.939,94.902 127.926,95.078 126.003,95.161 179.4,95.401 70.262,95.531 113.62,95.81 27.407,95.956 101.993,96.075 117.108,96.285 130.55,96.433 122.824,96.744 124.933,96.805 115.102,97.145 23.3,97.155 29.353,98.071 87.718,98.322 206.68,98.493 117.512,98.586 112.817,98.621 122.77,98.776 124.928,98.78 127.414,98.814 130.591,98.917 5.471,99.002 25.145,99.083 133.339,99.111 195.34,99.404 147.989,99.643 22.297,100.145 31.561,100.198 32.835,100.187 34.169,100.273 125.389,100.409 61.487,100.516 115.283,100.527 120.469,100.644 155.443,100.876 24.085,101.541 31.528,101.526 34.174,101.564 206.816,101.89 127.773,102.213 121.042,102.276 117.89,102.298 123.511,102.364 113.549,102.415 126.115,102.729 132.045,102.75 31.561,102.919 32.846,102.914 34.136,102.914 25.986,104.127 95.828,104.38 130.322,104.429 1.079,104.471 121.87,104.93 61.529,105.23 125.75,105.492 127.9,105.527 186.78,105.608 76.126,105.629 132.064,106.286 124.34,106.936 61.672,107.178 121.968,107.171 174.246,107.193 179.673,107.547 127.089,107.605 130.119,107.692 206.68,108.493 169.055,108.667 4.792,108.971 97.515,109.442 126.519,109.47 124.321,109.514 128.564,109.551 121.625,109.584 69.981,109.659 131.997,109.659 135.296,109.681 128.632,111.253 132.526,111.253 55.492,111.284 124.348,111.341 121.611,111.355 126.438,111.359 140.839,111.373 197.358,111.542 155.314,111.561 146.97,112.138 112.895,112.519 131.062,113.041 34.439,113.468 32.651,113.58 1.264,113.626 132.335,113.726 15.969,114.711 206.945,114.906 137.734,114.976 25.721,115.564 121.784,115.616 124.347,115.619 126.511,115.61 128.577,115.619 130.33,115.699 143.835,115.783 86.816,116.037 139.283,117.067 34.472,117.484 70.075,117.584 206.68,118.493 32.942,118.72 152.762,119.002 135.186,119.757 140.192,119.738 122.02,119.777 91.74,119.788 130.289,119.831 124.325,119.858 126.459,119.901 128.626,119.902 37.143,120.284 9.88,121.226 128.609,121.472 133.982,121.469 122.01,121.506 126.472,121.506 130.256,121.5 124.336,121.56 138.166,121.681 32.634,121.857 36.227,122.095 40.074,122.127 51.599,122.172 46.209,122.195 149.598,122.756 85.362,123.352 28.586,123.502 174.767,123.51 22.18,123.646 16.034,123.695 34.208,123.739 11.388,123.867 45.904,123.906 51.1,123.918 40.175,123.941 207.019,125.089 130.968,125.27 134.435,125.329 69.84,125.369 56.852,125.433 11.271,125.592 16.145,125.591 29.18,125.64 35.761,125.641 51.081,125.759 23.835,125.838 121.74,125.856 124.301,125.841 128.606,125.841 126.499,125.871 45.036,125.962 55.387,126.765 14.116,126.824 94.5,127.515 91.881,127.62 26.392,127.686 76.119,127.892 54.095,128.206 206.68,128.493 97.793,128.87 149.33,129.236 105.622,129.514 61.12,129.623 130.948,130.057 121.691,130.231 128.621,130.236 124.362,130.266 126.499,130.281 143.913,130.479 138.001,130.571 82.642,130.808 59.619,130.943 159.612,132.249 113.897,132.324 58.069,132.381 181.049,132.46 19.593,132.845 1.417,133.003 130.885,133.399 121.687,133.546 124.373,133.546 126.492,133.621 128.644,133.621 37.116,134.725 66.311,134.907 124.351,135.297 121.728,135.353 128.622,135.39 130.925,135.396 126.511,135.415 33.253,135.733 149.596,136.194 64.987,136.37 207.019,136.884 28.227,137.439 105.14,137.719 110.932,137.719 63.661,137.896 82.317,138.501 206.68,138.493 156.2,138.587 45.444,139.233 62.275,139.313 17.416,139.396 36.242,139.4 191.645,139.956 144.02,140.078 121.769,140.105 173.822,140.089 136.75,140.135 124.316,140.179 126.467,140.198 128.598,140.217 130.957,140.274 150.793,140.404 90.849,140.469 69.329,140.688 71.585,141.467 47.455,141.575 49.749,142.098 68.156,142.231 94.096,142.62 149.64,143.507 122.025,143.712 180.548,143.747 126.47,143.909 124.335,143.921 128.582,144.071 1.264,144.394 56.822,144.4 105.622,144.905 121.584,145.359 116.016,145.43 131.259,145.713 136.726,145.738 128.626,145.79 126.488,145.87 98.651,146.299 23.503,146.36 44.214,146.391 124.415,146.602 17.96,147.223 68.428,147.305 71.538,147.314 69.893,147.327 144.717,147.452 204.556,147.805 62.76,147.833 164.037,148.18 88.794,148.302 206.68,148.493 28.251,148.595 127.362,148.63 122.128,148.688 148.134,148.781 6.452,148.943 79.015,149.09 154.959,149.313 125.469,149.605 111.146,150.214 206.938,150.237 11.338,150.675 48.308,150.685 124.771,151.549 144.09,152.327 94.038,152.385 68.515,152.743 72.055,153.328 144.485,153.964 121.585,154.011 145.947,154.496 79.303,154.939 105.676,155.041 30.913,155.088 1.034,155.313 69.361,155.716 89.002,155.75 183.094,156.322 54.848,156.391 82.064,156.763 181.541,156.872 44.39,156.903 114.715,157.424 178.905,158.295 186.24,158.493 34.573,158.889 93.678,158.988 22.214,159.875 91.197,161.033 192.352,162.254 174.343,163.556 28.275,163.769 41.666,163.882 46.445,163.96 184.34,163.992 72.482,164.197 110.556,164.533 88.461,164.78 82.784,164.858 138.345,165.684 1.155,165.969 163.996,167.536 33.836,167.627 12.618,168.154 77.688,169.522 152.075,169.82 23.947,170.008 182.943,171.735 48.686,171.779 98.984,172.151 143.361,172.189 92.787,172.415 116.533,172.493 170.387,172.903 123.181,173.025 159.57,174.746 80.125,176.148 206.916,176.32 70.526,177.161 52.911,177.426 38.82,178.105 47.284,178.236 206.68,178.493 111.334,178.627 83.993,178.763 126.814,178.81 88.73,179.446 166.883,179.457 104.225,179.928 1.087,179.998 186.144,180.47 158.123,180.819 82.629,181.391 43.518,181.506 116.355,181.933 46.943,181.988 143.933,182.044 206.856,182.647 88.824,183.212 79.372,183.257 16.665,183.57 59.689,183.906 53.508,184.034 75.284,184.137 130.248,184.161 43.239,184.527 8.512,184.766 6.692,184.99 190.394,185.93 99.88,186.463 79.487,186.842 20.341,187.162 6.689,188.083 12.575,188.118 122.082,188.436 109.617,188.55 177.861,188.878 54.957,189.576 27.872,189.716 25.563,189.78 68.679,189.852 206.887,189.853 36.839,189.874 59.833,189.882 46.307,189.96 98.798,191.607 15.785,191.995 198.716,192.211 76.392,192.409 83.993,192.409 95.29,193.418 19.968,193.795 183.949,194.204 1.031,194.372 189.373,194.881 27.893,194.902 30.085,194.994 17.83,195.335 175.208,195.534 143.933,195.604 54.147,196.397 37.947,196.955 159.681,197.301 120.199,197.34 58.867,197.937 206.68,198.493 46.707,198.541 23.062,198.826 12.679,199.296 206.809,199.668 66.546,200.959 193.142,201.005 82.093,201.046 15.562,202.67 110.19,203.057 182.524,204.56 96.403,205.519 7.953,205.759 82.268,206.033 22.641,206.321 20.761,206.336 18.666,206.475 144.278,207.091 89.596,207.149 21.609,207.261 19.822,207.368 1.163,207.509 159.681,207.619 54.26,207.906 20.75,208.275 18.79,208.308 206.68,208.493 121.529,208.646 47.085,209.115 19.837,209.202 206.901,209.233 21.686,209.294 18.79,209.987 20.808,210.111 22.579,210.141 107.67,210.249 189.059,211.605 67.669,211.928 134.07,212.161 142.918,212.241 58.338,212.815 16.205,213.62 193.063,214.039 9.149,214.568 121.922,214.649 111.425,215.117 73.06,215.18 205.124,215.825 23.039,216.396 152.757,216.897 145.868,217.041 135.329,217.062 159.681,217.287 38.022,217.573 194.882,217.908 68.259,218.553 154.467,219.122 46.934,219.461 59.697,219.763 1.301,220.135 95.568,220.263 175.208,220.521 25.1,221.38 68.12,221.518 72.546,221.619 154.698,221.808 121.054,222.991 158.517,223.12 191.656,223.156 79.141,223.41 151.887,223.479 161.914,223.703 15.38,223.955 137.585,224.321 54.26,224.672 192.728,224.923 188.592,225.031 152.588,225.239 22.049,225.284 18.306,225.551 75.514,225.702 65.529,225.854 155.066,225.923 20.204,226.268 68.562,226.717 71.355,226.844 37.871,227.089 206.984,227.087 57.189,227.298 76.224,227.541 77.715,228.476 185.279,228.501 88.937,229.042 26.346,230.601 70.17,230.709 63.059,230.836 110.034,230.835 171.218,230.876 79.414,231.04 29.835,231.1 15.406,231.476 194.165,231.529 23.177,231.599 17.989,231.702 83.759,232.212 11.143,232.429 5.328,233.343 48.265,233.846 187.167,233.832 52.029,233.872 95.429,234.034 69.358,234.237 207.034,234.951 23.197,235.31 37.645,235.321 15.549,235.392 191.189,236.148 63.646,236.428 90.118,236.69 51.9,236.819 57.599,237.5 1.346,237.864 137.585,238.002 18.287,238.743 176.918,239.332 46.254,239.4 22.447,241.536 73.154,241.629 187.036,242.828 205.319,242.997 196.582,243.314 4.331,245.555 1.39,248.589 11.806,248.589 109.313,248.589 87.241,248.634 130.099,248.634 141.047,248.678 169.146,248.678 32.725,248.722 158.155,248.722 56.483,248.766 21.999,248.811 42.963,248.811 74.831,248.811 206.903,248.841 197.978,248.865 180.32,248.947 190.5,248.974
  other v3: 85.16,216.165 83.66,216.665 84.66,217.485 84.16,217.985
GPIO7: CN9.41 SB17.2 SB19.2 | length 5.1
  Top Layer w0.1: SB19.2@57.817,169.129 SB17.2@57.817,170.634 58.918,170.634 59.534,171.25 CN9.41@61.13,171.25
HDMI_CEC: CN10.93 CN11.51 | length 131.2
  Top Layer w0.1: v1(124.147,185.803) 121.671,183.327 121.671,155.862 123.31,154.223 128.484,154.223 129.457,153.25 CN10.93@131.13,153.25 ; CN11.51@202.87,176.75 202.9,176.72 v1(204.662,176.72)
  Bottom Layer w0.1: v1(124.147,185.803) 124.996,185.803 125.02,185.78 129.413,190.173 179.368,190.173 188.81,180.731 193.451,180.731 195.847,178.335 200.29,178.335 201.904,176.72 v1(204.662,176.72)
HDMI_PD: CN11.13 U20.11 | length 180.8
  Top Layer w0.1: U20.11@82.35,107.85 82.364,107.864 83.672,107.864 v1(83.684,107.875) ; v1(170.398,110.486) 197.81,110.486 201.028,113.704 v1(201.028,142.597) ; CN11.13@202.87,167.25 202.866,167.254 201.57,167.254 201.055,166.739 201.055,162.836 203.45,160.442 v1(203.906,160.442)
  Bottom Layer w0.1: v1(83.684,107.875) 105.734,107.875 108.345,110.486 v1(170.398,110.486) ; v1(201.028,142.597) 205.579,147.148 205.579,154.701 203.188,157.091 203.188,158.3 203.906,159.018 v1(203.906,160.442)
I2C2_SCL: CN10.79 CN11.53 CN19.44 R17.1 R49.2 R124.1 SB68.1 SB74.2 TR2.3 | length 471.3
  Top Layer w0.1: SB68.1@41.355,103.712 41.605,103.462 v1(41.605,102.536) ; v1(76.852,88.302) 76.86,88.309 R124.1@76.86,98.373 ; R49.2@85.98,211.525 86.052,211.525 86.725,210.852 87.861,210.852 92.356,206.357 92.356,189.173 97.496,184.033 v1(97.496,183.441) ; v1@115.73,82.512 115.75,82.531 CN19.44@115.75,85.13 ; v1(124.929,187.107) 124.929,185.673 122.119,182.863 122.119,156.073 123.485,154.707 128.924,154.707 129.378,155.162 129.378,156.203 129.925,156.75 132.627,156.75 133.594,155.783 133.594,154.773 134.821,153.546 134.821,131.763 153.146,113.437 153.146,98.334 v1(154.012,97.468) 154.025,97.455 155.178,97.455 SB74.2@155.27,97.364 ; v1(188.113,182.75) 187.628,183.235 187.628,201.459 v1(188.373,202.203) ; TR2.3@190.3,228.85 190.3,227.711 v1(190.302,227.709) ; TR2.3@190.339,228.822 190.257,228.903 190.257,230.492 190.95,231.184 R17.1@190.95,231.3 ; CN11.53@202.883,177.221 205.175,177.221 ; 205.186,177.225 v1(205.726,177.225)
  Bottom Layer w0.1: v1(41.605,102.536) 42.161,101.98 42.161,92.038 45.898,88.302 v1(76.852,88.302) 78.1,88.302 79.065,87.336 108.547,87.336 113.371,82.512 116.863,82.512 118.131,83.78 118.131,94.976 120.623,97.468 v1(154.012,97.468) ; v1(97.496,183.441) 120.738,183.441 124.403,187.107 v1(124.929,187.107) 125.571,187.107 129.105,190.641 179.474,190.641 186.781,183.334 187.53,183.334 v1(188.113,182.75) 189.551,181.313 193.507,181.313 196.134,178.686 200.624,178.686 202.085,177.225 v1(205.726,177.225) ; v1(188.373,202.203) 187.71,202.867 187.71,225.116 v1(190.302,227.709)
  other v1: 115.75,82.523
I2C2_SCL_C: CN7.13 R17.2 R20.1 TR2.2 | length 10.6
  Top Layer w0.1: R17.2@191.871,231.219 191.871,231.157 192.5,230.528 TR2.2@192.5,229.8 ; TR2.2@192.681,229.585 192.895,229.8 R20.1@194,229.8 ; R20.1@194.137,229.753 194.137,230.447 196.172,232.481 197.382,232.481 198.364,231.5 CN7.13@199.725,231.5
I2C2_SDA: CN10.78 CN11.55 CN19.40 R12.1 R50.2 R125.1 SB71.1 SB72.2 TR1.3 | length 468.5
  Top Layer w0.1: SB71.1@41.355,99.157 41.52,98.992 41.648,99.12 v1(42.79,99.12) ; v1(77.96,89.029) R125.1@77.96,98.373 ; R50.2@87.633,211.525 87.717,211.525 92.885,206.357 92.885,189.325 v1(98.133,184.077) ; v1@116.75,83.17 CN19.40@116.75,85.13 ; v1(123.553,155.693) 122.502,156.743 122.502,182.535 125.659,185.692 v1(125.659,188.003) ; CN10.78@136.87,157.25 135.014,157.25 v1(134.987,157.277) 134.987,156.058 134.625,155.695 134.625,154.143 135.26,153.508 135.26,132.166 153.621,113.805 153.621,99.416 v1(154.146,98.891) 154.17,98.915 SB72.2@155.276,98.915 ; v1(187.044,183.902) 187.044,184.499 187.296,184.751 v1(187.296,202.158) ; v1(188.572,228.454) 188.572,231.118 190.3,232.846 TR1.3@190.3,234.85 190.361,234.911 190.361,236.624 190.95,237.213 R12.1@190.95,237.35 ; CN11.55@202.87,177.75 202.877,177.757 202.889,177.745 204.455,177.745 v1(204.47,177.73)
  Bottom Layer w0.1: v1(42.79,99.12) 42.79,92.156 45.918,89.029 v1(77.96,89.029) 79.057,87.931 107.01,87.931 ; v1(98.133,184.077) 98.609,184.077 98.731,183.955 120.47,183.955 124.518,188.003 v1(125.659,188.003) 128.742,191.086 179.86,191.086 v1(187.044,183.902) 187.807,183.902 190.078,181.631 193.791,181.631 196.385,179.037 201.226,179.037 202.533,177.73 v1(204.47,177.73) ; 107.01,87.933 108.781,87.933 113.568,83.146 v1@116.709,83.146 ; v1@116.709,83.143 117.645,84.079 ; v1@116.712,83.143 v1@116.722,83.133 ; v1@116.722,83.153 117.645,84.075 117.645,84.079 ; v1(123.553,155.693) 133.403,155.693 v1(134.987,157.277) ; v1(154.146,98.891) 153.203,97.949 120.424,97.949 117.645,95.17 117.645,84.079 ; v1(187.296,202.158) 187.296,225.829 188.572,227.105 v1(188.572,228.454)
  other v1: 116.716,83.146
